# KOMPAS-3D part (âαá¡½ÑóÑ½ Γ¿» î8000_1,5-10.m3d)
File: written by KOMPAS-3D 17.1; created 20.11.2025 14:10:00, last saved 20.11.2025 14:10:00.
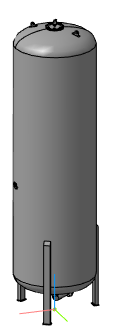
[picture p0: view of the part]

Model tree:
1. Операция без истории:1

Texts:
  REVIT MATERIAL OVERRIDDEN
  REVIT MATERIAL ID
  REVIT SUBCATEGORY ID
  REVIT CATEGORY ID
  REVIT ELEMENT ID
  REVIT BREP TAG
